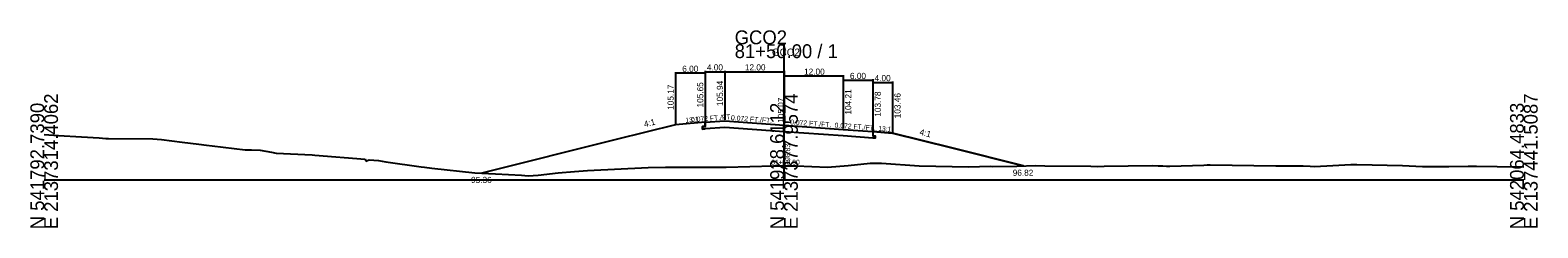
# Model space of a CAD drawing. Extents: x -14327 to 8886, y -10 to 39048.
# Drawn here: x 2997.2 to 3302.8, y 22990.3 to 23030.3 of the extents above; entities that cross this region are included whole.
import ezdxf

# ---------------------------------------------------------------- set-up
doc = ezdxf.new("R2010")
doc.units = 0
for name, color, linetype in [('Level 5', 7, 'Continuous'), ('Level 53', 7, 'Continuous'), ('Level 54', 7, 'Continuous'), ('Level 55', 7, 'Continuous'), ('Level 7', 7, 'Continuous'), ('RD_GPK_XS_Cell', 7, 'Continuous'), ('RD_XS_EwShp', 7, 'Continuous'), ('RD_XS_ExGround', 7, 'Continuous'), ('RD_XS_Pave', 7, 'Continuous'), ('RD_XS_TX_Baseline', 7, 'Continuous'), ('RD_XS_TX_Elev_EX', 7, 'Continuous'), ('RD_XS_TX_Elev_PR', 7, 'Continuous'), ('RD_XS_TX_Station', 7, 'Continuous')]:
    doc.layers.add(name, color=color, linetype=linetype)

msp = doc.modelspace()

# ---------------------------------------------------------------- linework, layer by layer
at = {"layer": 'Level 5'}
for p, q in [((3134, 23010.82), (3133.5, 23010.78)), ((3133.5, 23010.78), (3133.5, 23010.28)), ((3133.5, 23010.28), (3134, 23010.32)), ((3134, 23011.65), (3134, 23010.82)), ((3138, 23010.6), (3134, 23010.32)), ((3150, 23009.74), (3138, 23010.6)), ((3162, 23008.88), (3150, 23009.74)), ((3168, 23008.44), (3162, 23008.88)), ((3168, 23009.78), (3168, 23008.94)), ((3168, 23008.94), (3168.5, 23008.91)), ((3168.5, 23008.91), (3168.5, 23008.41)), ((3168.5, 23008.41), (3168, 23008.44))]:
    msp.add_line(p, q, dxfattribs=at)
at = {"layer": 'Level 54'}
for p, q in [((3128, 23021.8), (3128, 23011.37)), ((3134, 23021.6), (3128, 23021.6)), ((3134, 23022.09), (3134, 23011.85)), ((3134, 23021.89), (3138, 23021.89)), ((3134, 23021.8), (3134, 23011.85)), ((3138, 23022.09), (3138, 23012.14)), ((3138, 23021.89), (3150, 23021.89)), ((3150, 23022.09), (3150, 23011.27)), ((3150, 23021.22), (3150, 23011.27)), ((3150, 23021.02), (3162, 23021.02)), ((3162, 23021.22), (3162, 23010.41)), ((3162, 23020.36), (3162, 23010.41)), ((3162, 23020.16), (3168, 23020.16)), ((3168, 23020.36), (3168, 23009.98)), ((3168, 23019.93), (3168, 23009.98)), ((3168, 23019.73), (3172, 23019.73)), ((3172, 23019.93), (3172, 23009.66))]:
    msp.add_line(p, q, dxfattribs=at)
at = {"layer": 'Level 7'}
for p, q in [((3128, 23011.17), (3116, 23008.17)), ((3134, 23011.65), (3128, 23011.17)), ((3168, 23009.78), (3172, 23009.46)), ((3172, 23009.46), (3184, 23006.46)), ((3116, 23008.17), (3088.75, 23001.36)), ((3184, 23006.46), (3198.54, 23002.82))]:
    msp.add_line(p, q, dxfattribs=at)
at = {"layer": 'RD_GPK_XS_Cell'}
for p, q in [((3150, 23000), (3150, 23027.44)), ((3000, 23000), (3150, 23000)), ((3150, 23000), (3300, 23000))]:
    msp.add_line(p, q, dxfattribs=at)
at = {"layer": 'RD_XS_EwShp'}
msp.add_lwpolyline([(3088.75, 23001.36), (3091.48, 23001.21), (3096.79, 23000.96), (3098.11, 23000.85), (3100.16, 23000.96), (3104.24, 23001.4), (3107.51, 23001.69), (3110.17, 23001.92), (3122.49, 23002.52), (3125.95, 23002.58), (3135.63, 23002.57), (3136.91, 23002.54), (3138.29, 23002.57), (3147.88, 23002.82), (3150, 23002.83), (3152.45, 23002.85), (3158.84, 23002.56), (3163.04, 23002.94), (3167.5, 23003.4), (3169.8, 23003.41), (3177.42, 23002.87), (3187.5, 23002.62), (3191.81, 23002.76), (3192.21, 23002.7), (3197.21, 23002.79), (3198.54, 23002.82), (3184, 23006.46), (3172, 23009.46), (3168, 23009.78), (3168, 23008.94), (3168.5, 23008.91), (3168.5, 23008.41), (3168, 23008.44), (3162, 23008.88), (3150, 23009.74), (3138, 23010.6), (3134, 23010.32), (3133.5, 23010.28), (3133.5, 23010.78), (3134, 23010.82), (3134, 23011.65), (3128, 23011.17), (3116, 23008.17)], close=True, dxfattribs=at)
at = {"layer": 'RD_XS_ExGround'}
for p, q in [((3000, 23009.15), (3002.88, 23008.99)), ((3002.88, 23008.99), (3007.58, 23008.72)), ((3007.58, 23008.72), (3011.18, 23008.48)), ((3011.18, 23008.48), (3012.51, 23008.39)), ((3012.51, 23008.39), (3013.02, 23008.39)), ((3013.02, 23008.39), (3022, 23008.3)), ((3022, 23008.3), (3023.81, 23008.14)), ((3023.81, 23008.14), (3027.95, 23007.63)), ((3027.95, 23007.63), (3031.39, 23007.24)), ((3031.39, 23007.24), (3032.89, 23007.03)), ((3032.89, 23007.03), (3034.03, 23006.91)), ((3034.03, 23006.91), (3040.73, 23006.11)), ((3040.73, 23006.11), (3042.05, 23006.07)), ((3042.05, 23006.07), (3043.78, 23006.04)), ((3043.78, 23006.04), (3046.12, 23005.58)), ((3046.12, 23005.58), (3047.03, 23005.41)), ((3047.03, 23005.41), (3054.34, 23005.05)), ((3054.34, 23005.05), (3054.9, 23005)), ((3054.9, 23005), (3065.07, 23004.17)), ((3065.07, 23004.17), (3065.25, 23003.79)), ((3065.25, 23003.79), (3065.89, 23004.06)), ((3065.89, 23004.06), (3067.81, 23003.89)), ((3067.81, 23003.89), (3069.29, 23003.68)), ((3069.29, 23003.68), (3076.44, 23002.65)), ((3076.44, 23002.65), (3077.1, 23002.57)), ((3077.1, 23002.57), (3078.6, 23002.39)), ((3122.49, 23002.52), (3125.95, 23002.58)), ((3125.95, 23002.58), (3135.63, 23002.57)), ((3135.63, 23002.57), (3136.91, 23002.54)), ((3136.91, 23002.54), (3138.29, 23002.57)), ((3138.29, 23002.57), (3147.88, 23002.82)), ((3147.88, 23002.82), (3150, 23002.83)), ((3150, 23002.83), (3152.45, 23002.85)), ((3152.45, 23002.85), (3158.84, 23002.56)), ((3158.84, 23002.56), (3163.04, 23002.94)), ((3163.04, 23002.94), (3167.5, 23003.4)), ((3167.5, 23003.4), (3169.8, 23003.41)), ((3169.8, 23003.41), (3177.42, 23002.87)), ((3177.42, 23002.87), (3187.5, 23002.62)), ((3187.5, 23002.62), (3191.81, 23002.76)), ((3191.81, 23002.76), (3192.21, 23002.7)), ((3192.21, 23002.7), (3197.21, 23002.79)), ((3197.21, 23002.79), (3201.04, 23002.88)), ((3201.04, 23002.88), (3202.87, 23002.86)), ((3202.87, 23002.86), (3212.21, 23002.76)), ((3212.21, 23002.76), (3213.66, 23002.74)), ((3213.66, 23002.74), (3214.88, 23002.79)), ((3214.88, 23002.79), (3224.62, 23002.94)), ((3224.62, 23002.94), (3225.87, 23002.81)), ((3225.87, 23002.81), (3226.83, 23002.81)), ((3226.83, 23002.81), (3227.52, 23002.78)), ((3227.52, 23002.78), (3228.2, 23002.75)), ((3228.2, 23002.75), (3235.14, 23003.01)), ((3235.14, 23003.01), (3235.77, 23003.04)), ((3235.77, 23003.04), (3236.37, 23003.03)), ((3236.37, 23003.03), (3249.7, 23002.86)), ((3249.7, 23002.86), (3255.24, 23002.85)), ((3255.24, 23002.85), (3256.66, 23002.75)), ((3256.66, 23002.75), (3257.51, 23002.72)), ((3257.51, 23002.72), (3260.05, 23002.84)), ((3260.05, 23002.84), (3264.92, 23003.1)), ((3264.92, 23003.1), (3266.14, 23003.13)), ((3266.14, 23003.13), (3275.42, 23002.91)), ((3275.42, 23002.91), (3279.44, 23002.7)), ((3279.44, 23002.7), (3281.01, 23002.7)), ((3281.01, 23002.7), (3284.79, 23002.73)), ((3284.79, 23002.73), (3288.71, 23002.79)), ((3288.71, 23002.79), (3290.4, 23002.77)), ((3290.4, 23002.77), (3294.56, 23002.72)), ((3294.56, 23002.72), (3300, 23002.66)), ((3078.6, 23002.39), (3087.33, 23001.43)), ((3087.33, 23001.43), (3091.48, 23001.21)), ((3091.48, 23001.21), (3096.79, 23000.96)), ((3096.79, 23000.96), (3098.11, 23000.85)), ((3098.11, 23000.85), (3100.16, 23000.96)), ((3100.16, 23000.96), (3104.24, 23001.4)), ((3104.24, 23001.4), (3107.51, 23001.69)), ((3107.51, 23001.69), (3110.17, 23001.92)), ((3110.17, 23001.92), (3122.49, 23002.52))]:
    msp.add_line(p, q, dxfattribs=at)
at = {"layer": 'RD_XS_Pave'}
for p, q in [((3134, 23011.65), (3138, 23011.94)), ((3138, 23011.94), (3150, 23011.07)), ((3150, 23011.07), (3162, 23010.21)), ((3162, 23010.21), (3168, 23009.78))]:
    msp.add_line(p, q, dxfattribs=at)

# ---------------------------------------------------------------- texts
at = {"layer": 'Level 53'}
for s, rotation, p in [('105.17', 90, (3127.63, 23014.17)), ('105.65', 90, (3133.63, 23014.65)), ('105.94', 90, (3137.63, 23014.94)), ('104.21', 90, (3163.63, 23013.21)), ('103.78', 90, (3169.63, 23012.78)), ('103.46', 90, (3173.63, 23012.46)), ('4:1', 14.0362, (3121.76, 23010.64)), ('4:1', 345.9638, (3177.39, 23009.14))]:
    msp.add_text(s, height=1.25, rotation=rotation, dxfattribs=at).set_placement(p)
for s, p in [('95.36', (3086.55, 22999.36)), ('96.82', (3196.37, 23000.82))]:
    msp.add_text(s, height=1.25, dxfattribs=at).set_placement(p)
at = {"layer": 'Level 54'}
for s, p in [('6.00', (3129.37, 23021.85)), ('4.00', (3134.37, 23022.14)), ('12.00', (3142.07, 23022.14)), ('12.00', (3154.07, 23021.27)), ('6.00', (3163.37, 23020.41)), ('4.00', (3168.37, 23019.98))]:
    msp.add_text(s, height=1.25, dxfattribs=at).set_placement(p)
at = {"layer": 'Level 55'}
for s, rotation, p in [('13:1', 4.5739, (3130.03, 23011.58)), ('0.072 FT./FT.', 4.1182, (3131.18, 23011.7)), ('0.072 FT./FT.', 355.8818, (3139.22, 23012.1)), ('0.072 FT./FT.', 355.8818, (3151.22, 23011.24)), ('0.072 FT./FT.', 355.8818, (3160.22, 23010.59)), ('13:1', 355.4261, (3169.07, 23009.94))]:
    msp.add_text(s, height=1, rotation=rotation, dxfattribs=at).set_placement(p)
at = {"layer": 'RD_GPK_XS_Cell'}
for s, p in [('GCO2', (3140, 23027.44)), ('81+50.00 / 1', (3140, 23024.64))]:
    msp.add_text(s, height=2.8, dxfattribs=at).set_placement(p)
for s, p in [('N 541792.7390', (3000, 22990)), ('E 2137314.4062', (3002.8, 22990)), ('N 541928.6112', (3150, 22990)), ('E 2137377.9574', (3152.8, 22990)), ('N 542064.4833', (3300, 22990)), ('E 2137441.5087', (3302.8, 22990))]:
    msp.add_text(s, height=2.8, rotation=90, dxfattribs=at).set_placement(p)
at = {"layer": 'RD_XS_TX_Baseline'}
msp.add_text('GCO2', height=1.5, dxfattribs=at).set_placement((3147.55, 23025.07))
at = {"layer": 'RD_XS_TX_Elev_EX'}
msp.add_text('96.83', height=1, rotation=90, dxfattribs=at).set_placement((3151.25, 23003.83))
at = {"layer": 'RD_XS_TX_Elev_PR'}
msp.add_text(' 105.07', height=1.25, rotation=90, dxfattribs=at).set_placement((3150, 23011.07))
at = {"layer": 'RD_XS_TX_Station'}
msp.add_text('81+50.00', height=1, dxfattribs=at).set_placement((3147.4, 23003.07))

doc.saveas('drawing.dxf')
